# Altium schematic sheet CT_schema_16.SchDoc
size 389 x 385 mm
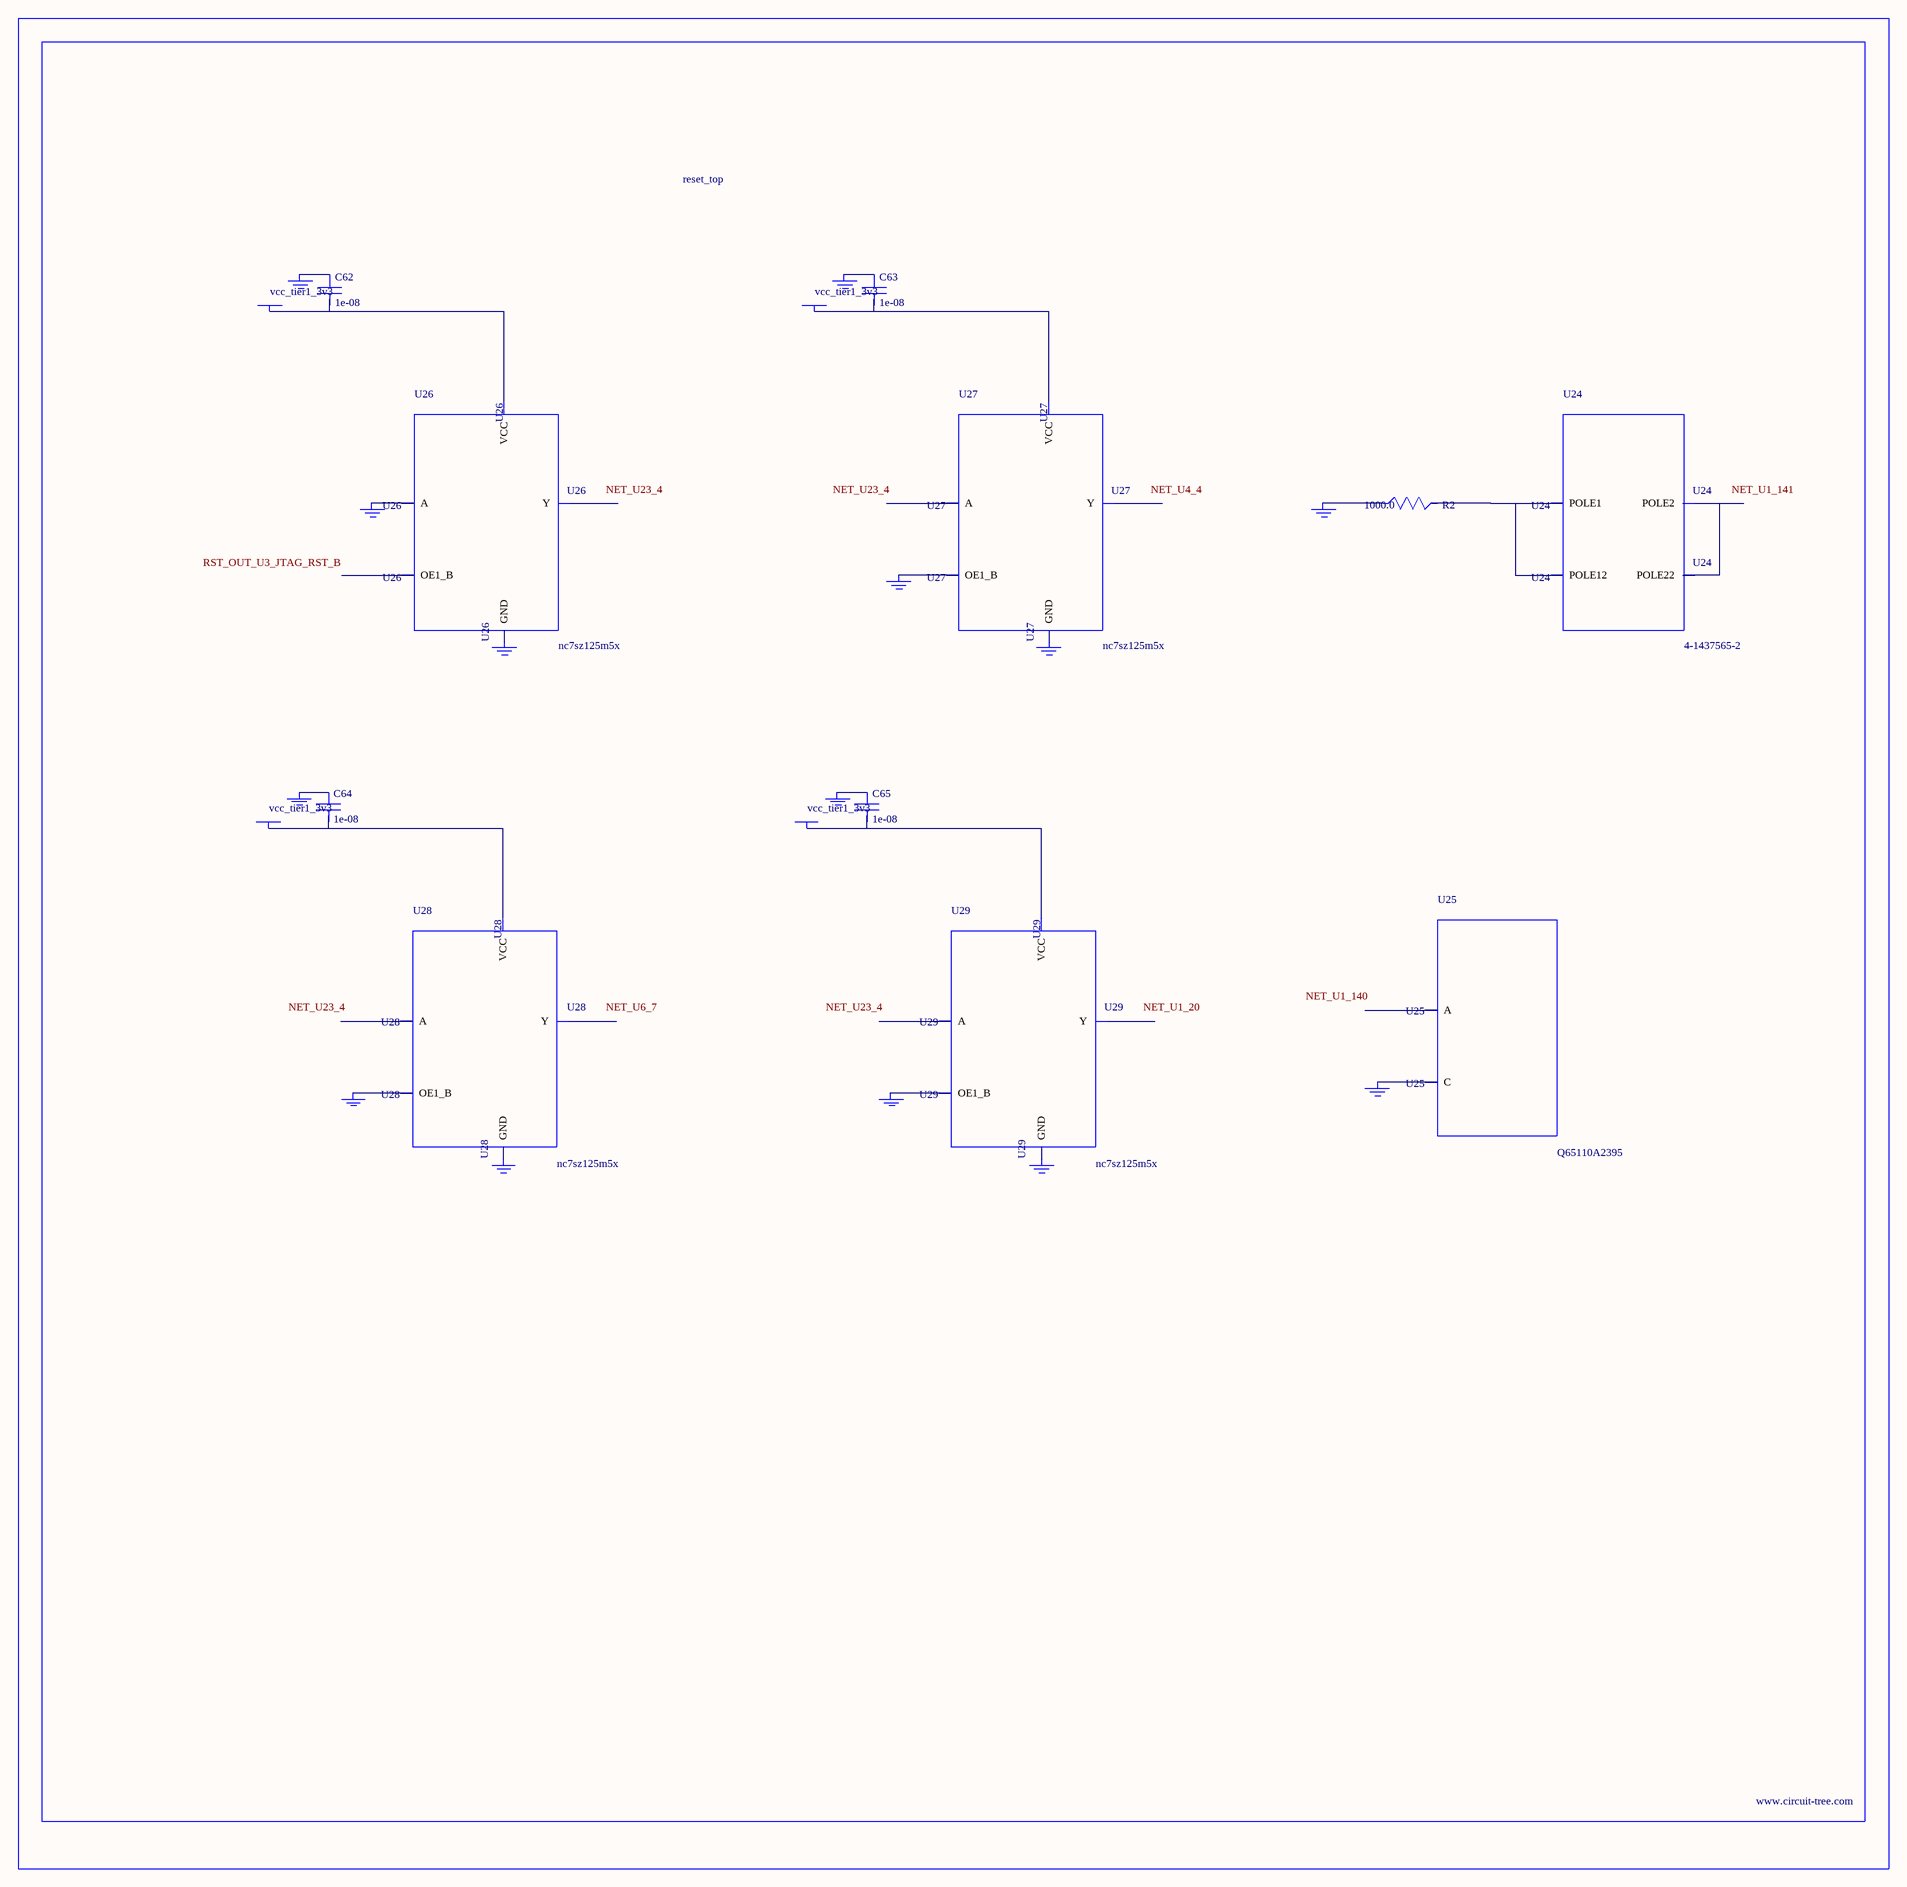
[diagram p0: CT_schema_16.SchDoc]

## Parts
BORDER15  (no value)
C62  1e-08  [C0402]
C63  1e-08  [C0402]
C64  1e-08  [C0402]
C65  1e-08  [C0402]
GND_INSTANCE_15_0  (no value)
GND_INSTANCE_15_1  (no value)
GND_INSTANCE_15_2  (no value)
GND_INSTANCE_15_3  (no value)
GND_INSTANCE_15_4  (no value)
GND_INSTANCE_15_5  (no value)
GND_INSTANCE_15_6  (no value)
GND_INSTANCE_15_7  (no value)
GND_INSTANCE_15_8  (no value)
GND_INSTANCE_15_9  (no value)
GND_INSTANCE_15_10  (no value)
GND_INSTANCE_15_11  (no value)
GND_INSTANCE_15_12  (no value)
GND_INSTANCE_15_13  (no value)
POWER_INSTANCE_15_0  vcc_tier1_3v3
POWER_INSTANCE_15_1  vcc_tier1_3v3
POWER_INSTANCE_15_2  vcc_tier1_3v3
POWER_INSTANCE_15_3  vcc_tier1_3v3
R2  1000.0  [R0603]
U24  4-1437565-2  [SW_4-1437565-2]
U25  Q65110A2395  [LGM67K-G1J2-24-Z]
U26  nc7sz125m5x  [NC7SZ125M5X]
U27  nc7sz125m5x  [NC7SZ125M5X]
U28  nc7sz125m5x  [NC7SZ125M5X]
U29  nc7sz125m5x  [NC7SZ125M5X]

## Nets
NetC62_1: C62.1 GND_INSTANCE_15_2.0(GND)
NetC62_2: C62.2 POWER_INSTANCE_15_0.0(PWR) U26.5(VCC)
NetC63_1: C63.1 GND_INSTANCE_15_5.0(GND)
NetC63_2: C63.2 POWER_INSTANCE_15_1.0(PWR) U27.5(VCC)
NetC64_1: C64.1 GND_INSTANCE_15_8.0(GND)
NetC64_2: C64.2 POWER_INSTANCE_15_2.0(PWR) U28.5(VCC)
NetC65_1: C65.1 GND_INSTANCE_15_11.0(GND)
NetC65_2: C65.2 POWER_INSTANCE_15_3.0(PWR) U29.5(VCC)
NetGND_INSTANCE_15_0_0: GND_INSTANCE_15_0.0(GND) R2.1
NetGND_INSTANCE_15_1_0: GND_INSTANCE_15_1.0(GND) U25.C
NetGND_INSTANCE_15_3_0: GND_INSTANCE_15_3.0(GND) U26.2(A)
NetGND_INSTANCE_15_4_0: GND_INSTANCE_15_4.0(GND) U26.3(GND)
NetGND_INSTANCE_15_6_0: GND_INSTANCE_15_6.0(GND) U27.1(OE1_B)
NetGND_INSTANCE_15_7_0: GND_INSTANCE_15_7.0(GND) U27.3(GND)
NetGND_INSTANCE_15_9_0: GND_INSTANCE_15_9.0(GND) U28.1(OE1_B)
NetGND_INSTANCE_15_10_0: GND_INSTANCE_15_10.0(GND) U28.3(GND)
NetGND_INSTANCE_15_12_0: GND_INSTANCE_15_12.0(GND) U29.1(OE1_B)
NetGND_INSTANCE_15_13_0: GND_INSTANCE_15_13.0(GND) U29.3(GND)
NetR2_2: R2.2 U24.1(POLE1) U24.2(POLE12)
NetU24_3: U24.3(POLE2) U24.4(POLE22)

Not connected (* = marked no-connect by the designer): U25 A; U26 1(OE1_B) 4(Y); U27 2(A) 4(Y); U28 2(A) 4(Y); U29 2(A) 4(Y)

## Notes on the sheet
- Labels drawn without touching a wire or pin: NET_U1_20, NET_U1_140, NET_U1_141, NET_U4_4, NET_U6_7, NET_U23_4, RST_OUT_U3_JTAG_RST_B

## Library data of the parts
BORDER15 = BORDER_PAGE15
C62-C65 = C0402C103K3RAC
GND_INSTANCE_15_0-GND_INSTANCE_15_13 = GND
POWER_INSTANCE_15_0-POWER_INSTANCE_15_3 = PWR
R2 = RC0603JR-071KL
